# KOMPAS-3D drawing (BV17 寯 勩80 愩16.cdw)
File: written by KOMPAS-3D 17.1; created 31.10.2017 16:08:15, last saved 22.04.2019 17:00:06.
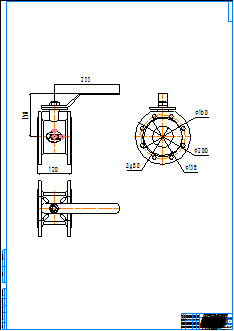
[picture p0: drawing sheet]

Sheet 1: A0, portrait

Title block, sheet 1: name: BV17 МФ Ду80 Ру16; material: Внимание! Данный продукт является объектом авторского права ООО «Торговый Дом АДЛ». / Запрещается изменение, копирование, распространение / (в том числе путем копирования на другие сайты и ресурсы в Интернете) / или любое иное использование информации и объектов без предварительного / согласия правообладателя (ООО «Торговый Дом АДЛ»).; mass: 1; sheets: 1; organisation: ООО "Торговый дом АДЛ"; sheet format: A0; stored path: \\adlc.lan\data\АДЛ_ПКД\3D-модели\ADL production\Краны шаровые серии BV\BV17 МФ Нержавеющие Ру16\KOMPAS 2D\BV17 МФ Ду80 Ру16.cdw

Views: Вид 1, Проекционный вид 2, Проекционный вид 3
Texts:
  kka
  adl
Dimensions and other numbers on the sheet: 120; 158; 233; 80; 200; 160; 138; 1:1; 1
